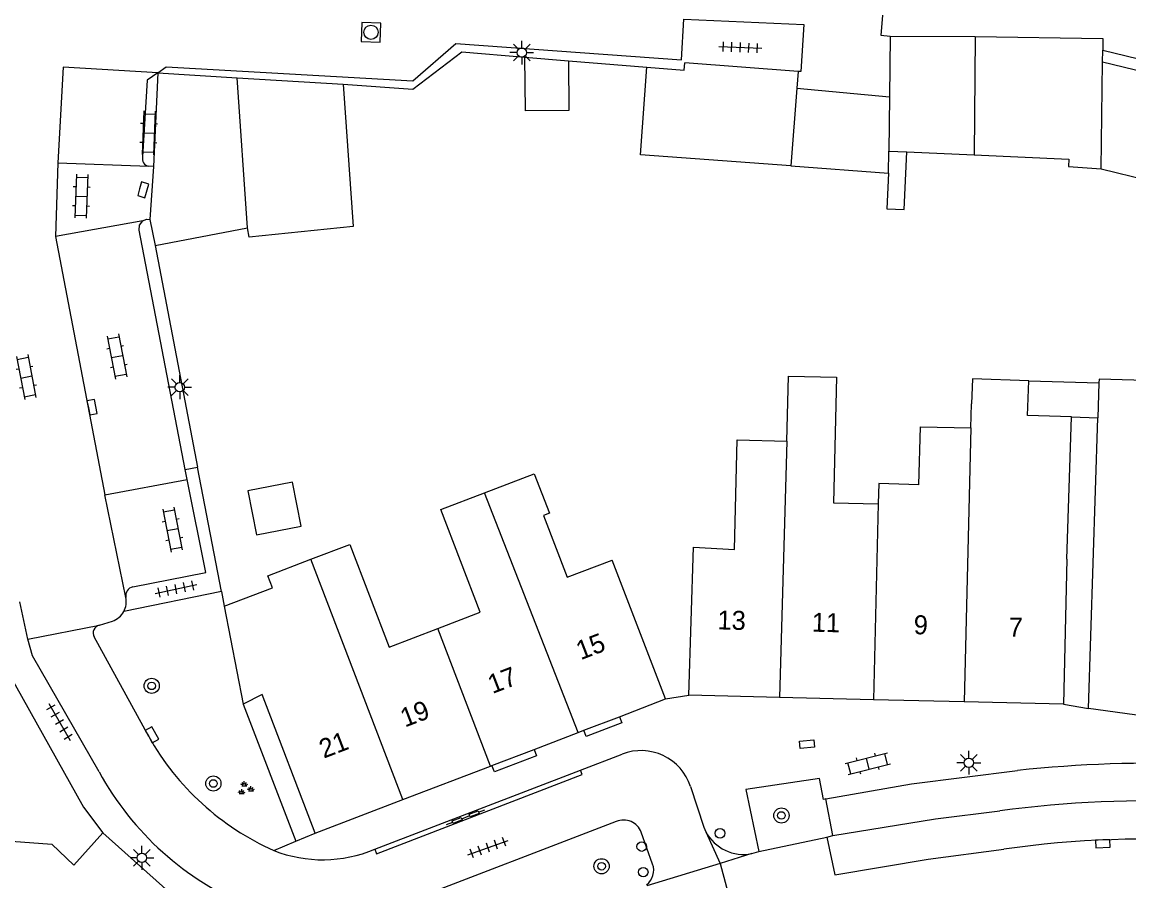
# Model space of a CAD drawing. Extents: x 132998 to 136004, y 396998 to 398512.
# Drawn here: x 133190.8 to 133249, y 397789.9 to 397835.1 of the extents above; entities that cross this region are included whole.
import ezdxf

# ---------------------------------------------------------------- set-up
doc = ezdxf.new("R2010")
doc.units = 0
for name, color, linetype in [('gg-afsc-erfafscheiding', 7, 'Continuous'), ('gg-afsc-muur', 7, 'Continuous'), ('gg-anno-huisnummerreeks BGT', 7, 'Continuous'), ('gg-bbg-bijgebouw', 7, 'Continuous'), ('gg-bbg-gedigitaliseerde bebouwing', 7, 'Continuous'), ('gg-bbg-gedigitaliseerde bijgebouw', 7, 'Continuous'), ('gg-bbg-hoofdgebouw', 7, 'Continuous'), ('gg-bbg-luifel en loopbrug', 7, 'Continuous'), ('gg-bbg-tussenscheiding', 7, 'Continuous'), ('gg-knt-verharding', 7, 'Continuous'), ('gg-knt-verharding nz', 7, 'Continuous'), ('gt-grn-afwateringsgoot', 7, 'Continuous'), ('gt-grn-weggrens', 7, 'Continuous'), ('gt-symb-afwateringsgoot', 7, 'Continuous'), ('gt-symb-boom', 7, 'Continuous'), ('gt-symb-drukknoppaal', 7, 'Continuous'), ('gt-symb-groenvak', 7, 'Continuous'), ('gt-symb-klinker verharding', 7, 'Continuous'), ('gt-symb-kolk', 7, 'Continuous'), ('gt-symb-kolk center center', 7, 'Continuous'), ('gt-symb-lichtmast', 7, 'Continuous'), ('gt-symb-rioolschacht', 7, 'Continuous'), ('gt-symb-tegel verharding', 7, 'Continuous'), ('gt-symb-verkeersregelinstallatiepaal', 7, 'Continuous')]:
    doc.layers.add(name, color=color, linetype=linetype)

# ---------------------------------------------------------------- blocks, each defined once
blk = doc.blocks.new('gt0-TEG1')
at = {"layer": 'gt-symb-tegel verharding'}
for p, q in [((-1.125, 0), (1.125, 0)), ((-0.9, -0.25), (-0.9, 0.25)), ((-0.45, -0.25), (-0.45, 0.25)), ((0, -0.25), (0, 0.25)), ((0.45, -0.25), (0.45, 0.25)), ((0.9, -0.25), (0.9, 0.25))]:
    blk.add_line(p, q, dxfattribs=at)
blk = doc.blocks.new('gt0-AFWGT_1')
at = {"layer": 'gt-symb-afwateringsgoot'}
for p, q in [((-1.076, 0), (-0.726, 0)), ((-0.225, 0), (0.225, 0)), ((0.725, 0), (1.075, 0))]:
    blk.add_line(p, q, dxfattribs=at)
for points in [[(-0.726, 0.075), (-0.225, 0.075), (-0.225, -0.075), (-0.726, -0.075)], [(0.225, 0.075), (0.725, 0.075), (0.725, -0.075), (0.225, -0.075)]]:
    blk.add_lwpolyline(points, close=True, dxfattribs=at)
blk = doc.blocks.new('gt0-LMAST')
at = {"layer": 'gt-symb-lichtmast'}
for p, q in [((-0.005, 0.246), (-0.005, 0.621)), ((-0.182, 0.173), (-0.447, 0.438)), ((0.172, 0.173), (0.437, 0.438)), ((-0.255, -0.004), (-0.63, -0.004)), ((-0.182, -0.181), (-0.447, -0.446)), ((-0.005, -0.254), (-0.005, -0.629)), ((0.437, -0.446), (0.172, -0.181)), ((0.245, -0.004), (0.62, -0.004))]:
    blk.add_line(p, q, dxfattribs=at)
blk.add_circle((-0.005, -0.004), 0.25, dxfattribs=at)
blk = doc.blocks.new('gt0-RS')
at = {"layer": 'gt-symb-rioolschacht'}
blk.add_lwpolyline([(-0.5, -0.5), (0.5, -0.5), (0.5, 0.5), (-0.5, 0.5)], close=True, dxfattribs=at)
blk.add_circle((0, 0), 0.375, dxfattribs=at)
blk = doc.blocks.new('gt0-KL1')
at = {"layer": 'gt-symb-klinker verharding'}
for p, q in [((-1.15, 0.3), (1.15, 0.3)), ((-1, -0.3), (-1, 0.3)), ((-0.5, 0.3), (-0.5, 0.45)), ((0, -0.3), (0, 0.3)), ((0.5, 0.3), (0.5, 0.45)), ((1, -0.3), (1, 0.3)), ((-1.15, -0.3), (1.15, -0.3)), ((-0.5, -0.45), (-0.5, -0.3)), ((0.5, -0.45), (0.5, -0.3))]:
    blk.add_line(p, q, dxfattribs=at)
blk = doc.blocks.new('gt0-KOLK')
at = {"layer": 'gt-symb-kolk'}
blk.add_lwpolyline([(0, 0), (0.375, 0), (0.375, 0.4), (-0.375, 0.4), (-0.375, 0), (0, 0)], dxfattribs=at)
blk = doc.blocks.new('gt0-BOOM')
at = {"layer": 'gt-symb-boom'}
for radius in [0.4, 0.2]:
    blk.add_circle((0, 0), radius, dxfattribs=at)
blk = doc.blocks.new('gt0-KOLKCC')
at = {"layer": 'gt-symb-kolk center center'}
blk.add_lwpolyline([(-0.375, 0.2), (0.375, 0.2), (0.375, -0.2), (-0.375, -0.2)], close=True, dxfattribs=at)
blk = doc.blocks.new('gt0-VIPAAL')
at = {"layer": 'gt-symb-verkeersregelinstallatiepaal'}
blk.add_circle((0, 0), 0.25, dxfattribs=at)
blk = doc.blocks.new('gt0-GRVAK')
at = {"layer": 'gt-symb-groenvak'}
for p, q in [((-0.11, 0.189), (-0.228, 0.24)), ((-0.182, 0.153), (0.088, 0.153)), ((-0.091, 0.211), (-0.156, 0.322)), ((-0.047, 0.214), (-0.047, 0.393)), ((-0.004, 0.211), (0.061, 0.322)), ((0.015, 0.189), (0.133, 0.24)), ((0.262, -0.052), (0.197, 0.059)), ((0.305, -0.049), (0.305, 0.13)), ((0.349, -0.052), (0.414, 0.059)), ((-0.245, -0.228), (-0.363, -0.177)), ((-0.318, -0.264), (-0.047, -0.264)), ((-0.226, -0.206), (-0.291, -0.095)), ((-0.183, -0.203), (-0.183, -0.024)), ((-0.139, -0.206), (-0.074, -0.095)), ((-0.12, -0.228), (-0.002, -0.177)), ((0.243, -0.074), (0.125, -0.023)), ((0.17, -0.11), (0.441, -0.11)), ((0.368, -0.074), (0.486, -0.023))]:
    blk.add_line(p, q, dxfattribs=at)
blk = doc.blocks.new('gt0-DPAAL')
at = {"layer": 'gt-symb-drukknoppaal'}
blk.add_circle((0, 0), 0.25, dxfattribs=at)

msp = doc.modelspace()

# ---------------------------------------------------------------- linework, layer by layer
at = {"layer": 'gg-afsc-erfafscheiding'}
for p, q in [((133219.534, 397833.102), (133223.664, 397832.759)), ((133197.777, 397823.375), (133200.006, 397811.718)), ((133201.273, 397805.159), (133200.006, 397811.718)), ((133201.273, 397805.159), (133201.422, 397804.389))]:
    msp.add_line(p, q, dxfattribs=at)
msp.add_lwpolyline([(133207.68, 397831.857), (133211.339, 397831.605), (133213.924, 397833.569), (133217.238, 397833.293)], dxfattribs=at)
at = {"layer": 'gg-afsc-muur'}
msp.add_lwpolyline([(133189.223, 397804.078), (133189.752, 397801.443), (133194.013, 397793.822), (133195.025, 397792.466)], dxfattribs=at)
at = {"layer": 'gg-bbg-bijgebouw'}
for p, q in [((133236.46, 397834.4), (133236.423, 397831.203)), ((133225.621, 397832.596), (133225.65, 397832.99)), ((133231.62, 397832.54), (133225.65, 397832.99)), ((133197.921, 397832.455), (133197.706, 397827.537)), ((133197.921, 397832.455), (133202.099, 397832.199)), ((133202.099, 397832.199), (133207.68, 397831.857)), ((133231.62, 397832.54), (133231.553, 397831.663)), ((133231.553, 397831.663), (133236.423, 397831.203)), ((133197.706, 397827.537), (133197.513, 397824.75)), ((133197.513, 397824.75), (133197.777, 397823.375))]:
    msp.add_line(p, q, dxfattribs=at)
msp.add_lwpolyline([(133236.28, 397838.22), (133235.97, 397834.45), (133236.46, 397834.4)], dxfattribs=at)
at = {"layer": 'gg-bbg-gedigitaliseerde bebouwing'}
for p, q in [((133247.449, 397816.142), (133247.39, 397814.304)), ((133240.715, 397813.775), (133240.746, 397815.037)), ((133245.763, 397806.866), (133246, 397814.365)), ((133246.9, 397799.01), (133247.39, 397814.304)), ((133215.111, 397810.358), (133217.735, 397811.363)), ((133245.763, 397806.866), (133245.58, 397799.23)), ((133201.422, 397804.389), (133202.422, 397799.232)), ((133203.422, 397799.747), (133202.422, 397799.232))]:
    msp.add_line(p, q, dxfattribs=at)
for points in [[(133231.019, 397813.081), (133231.108, 397816.501), (133233.638, 397816.439), (133233.472, 397809.84), (133235.829, 397809.783)], [(133243.754, 397816.259), (133240.788, 397816.353), (133240.746, 397815.037)], [(133246, 397814.365), (133243.696, 397814.437), (133243.754, 397816.259)], [(133250.496, 397816.253), (133247.456, 397816.349), (133247.449, 397816.142)], [(133237.977, 397810.783), (133238.051, 397813.84), (133240.715, 397813.775)], [(133226.108, 397807.493), (133228.277, 397807.369), (133228.418, 397813.144), (133231.019, 397813.081)], [(133217.735, 397811.363), (133218.532, 397809.283), (133218.226, 397809.166), (133219.468, 397805.916), (133221.838, 397806.821)], [(133237.977, 397810.783), (133235.863, 397810.85), (133235.829, 397809.783)], [(133212.658, 397803.219), (133214.886, 397804.072), (133212.816, 397809.479), (133215.111, 397810.358)], [(133205.98, 397806.862), (133208.025, 397807.645), (133210.095, 397802.238), (133212.658, 397803.219)], [(133201.422, 397804.389), (133203.964, 397805.362), (133203.721, 397805.997), (133205.98, 397806.862)]]:
    msp.add_lwpolyline(points, dxfattribs=at)
at = {"layer": 'gg-bbg-gedigitaliseerde bijgebouw'}
for p, q in [((133247.638, 397833.028), (133247.646, 397833.659)), ((133223.664, 397832.759), (133225.621, 397832.596)), ((133236.377, 397827.181), (133236.39, 397828.34)), ((133236.39, 397828.34), (133237.333, 397828.298)), ((133237.333, 397828.298), (133240.877, 397828.142)), ((133231.24, 397827.56), (133236.377, 397827.181)), ((133197.777, 397823.375), (133202.644, 397824.308))]:
    msp.add_line(p, q, dxfattribs=at)
for points in [[(133247.646, 397833.659), (133252.629, 397832.444), (133253.676, 397836.864), (133252.071, 397836.978)], [(133231.24, 397827.56), (133223.322, 397828.155), (133223.664, 397832.759)], [(133247.568, 397827.408), (133254.881, 397825.625), (133256.178, 397830.946), (133247.638, 397833.028)], [(133207.68, 397831.857), (133208.197, 397824.375), (133202.725, 397823.814), (133202.644, 397824.308)], [(133240.877, 397828.142), (133245.863, 397827.922), (133245.846, 397827.539), (133247.568, 397827.408)]]:
    msp.add_lwpolyline(points, dxfattribs=at)
at = {"layer": 'gg-bbg-hoofdgebouw'}
for p, q in [((133225.87, 397799.71), (133226.108, 397807.493)), ((133224.64, 397799.51), (133221.838, 397806.821)), ((133206.21, 397792.45), (133203.422, 397799.747)), ((133222.212, 397798.58), (133224.64, 397799.51)), ((133230.646, 397799.594), (133225.87, 397799.71)), ((133235.578, 397799.474), (133230.646, 397799.594)), ((133240.364, 397799.357), (133235.578, 397799.474)), ((133245.58, 397799.23), (133240.364, 397799.357)), ((133252.318, 397798.26), (133246.9, 397799.01)), ((133220.344, 397797.865), (133222.212, 397798.58)), ((133217.723, 397796.861), (133220.037, 397797.747)), ((133220.037, 397797.747), (133220.344, 397797.865)), ((133215.51, 397796.013), (133217.723, 397796.861)), ((133210.821, 397794.216), (133215.429, 397795.982)), ((133215.429, 397795.982), (133215.51, 397796.013)), ((133206.21, 397792.45), (133210.821, 397794.216)), ((133195.025, 397792.466), (133201.316, 397786.868))]:
    msp.add_line(p, q, dxfattribs=at)
msp.add_lwpolyline([(133182.882, 397792.565), (133192.357, 397791.868), (133193.511, 397790.761), (133195.025, 397792.466)], dxfattribs=at)
at = {"layer": 'gg-bbg-luifel en loopbrug'}
for p, q in [((133217.238, 397833.293), (133219.534, 397833.102)), ((133243.754, 397816.259), (133247.449, 397816.142)), ((133246, 397814.365), (133247.39, 397814.304))]:
    msp.add_line(p, q, dxfattribs=at)
for points in [[(133219.534, 397833.102), (133219.559, 397830.487), (133217.265, 397830.465), (133217.238, 397833.293)], [(133236.377, 397827.181), (133236.294, 397825.304), (133237.199, 397825.264), (133237.333, 397828.298)], [(133202.664, 397810.468), (133203.11, 397808.145), (133205.461, 397808.597), (133205.015, 397810.919), (133202.664, 397810.468)]]:
    msp.add_lwpolyline(points, dxfattribs=at)
at = {"layer": 'gg-bbg-tussenscheiding'}
for p, q in [((133236.46, 397834.4), (133240.939, 397834.372)), ((133240.939, 397834.372), (133240.877, 397828.142)), ((133247.568, 397827.408), (133247.638, 397833.028)), ((133202.644, 397824.308), (133202.099, 397832.199)), ((133231.553, 397831.663), (133231.24, 397827.56)), ((133236.423, 397831.203), (133236.39, 397828.34)), ((133240.715, 397813.775), (133240.364, 397799.357)), ((133231.019, 397813.081), (133230.646, 397799.594)), ((133220.037, 397797.747), (133215.111, 397810.358)), ((133235.829, 397809.783), (133235.578, 397799.474)), ((133210.821, 397794.216), (133205.98, 397806.862)), ((133215.429, 397795.982), (133212.658, 397803.219))]:
    msp.add_line(p, q, dxfattribs=at)
msp.add_lwpolyline([(133240.939, 397834.372), (133247.654, 397834.267), (133247.646, 397833.659)], dxfattribs=at)
at = {"layer": 'gg-knt-verharding'}
for p, q in [((133197.921, 397832.455), (133198.368, 397832.785)), ((133197.706, 397827.537), (133197.45, 397827.545)), ((133199.361, 397811.594), (133200.006, 397811.718)), ((133199.463, 397811.06), (133199.361, 397811.594)), ((133201.273, 397805.159), (133196.136, 397804.119)), ((133191.09, 397802.651), (133190.658, 397804.629)), ((133194.852, 397803.389), (133195.538, 397803.61)), ((133191.09, 397802.651), (133194.852, 397803.389)), ((133197.445, 397797.529), (133194.576, 397802.773)), ((133224.64, 397799.51), (133225.87, 397799.71)), ((133202.422, 397799.232), (133205.195, 397792.027)), ((133245.58, 397799.23), (133246.9, 397799.01)), ((133220.17, 397795.772), (133222.364, 397796.608)), ((133233.445, 397792.333), (133233.078, 397794.249)), ((133222.049, 397793.056), (133210.736, 397788.714)), ((133223.962, 397790.826), (133223.366, 397792.504)), ((133204.025, 397791.539), (133205.195, 397792.027)), ((133205.195, 397792.027), (133206.21, 397792.45)), ((133229.543, 397791.489), (133233.132, 397792.247)), ((133233.132, 397792.247), (133233.445, 397792.333)), ((133229.18, 397791.372), (133227.519, 397790.861)), ((133229.18, 397791.372), (133229.543, 397791.489)), ((133227.519, 397790.861), (133223.656, 397789.673))]:
    msp.add_line(p, q, dxfattribs=at)
for points in [[(133198.368, 397832.785), (133211.34, 397832.04), (133213.61, 397834), (133225.48, 397833.14), (133225.61, 397835.28), (133231.92, 397835.01), (133231.759, 397832.531), (133231.62, 397832.54)], [(133197.921, 397832.455), (133197.367, 397832.07), (133197.126, 397828.05)], [(133199.361, 397811.594), (133196.949, 397824.174), (133196.968, 397824.452), (133197.137, 397824.673)], [(133197.137, 397824.673), (133197.329, 397824.756), (133197.513, 397824.75)], [(133196.606, 397805.418), (133200.454, 397806.166), (133199.463, 397811.06)], [(133194.838, 397795.676), (133191.338, 397801.785), (133191.09, 397802.651)], [(133222.212, 397798.58), (133222.337, 397798.253), (133220.47, 397797.538), (133220.344, 397797.865)], [(133217.723, 397796.861), (133217.852, 397796.525), (133215.639, 397795.677), (133215.51, 397796.013)], [(133233.078, 397794.249), (133237.58, 397795.038), (133243.167, 397795.755)], [(133225.948, 397794.908), (133226.656, 397792.768), (133226.766, 397792.524)], [(133233.078, 397794.249), (133232.954, 397794.228), (133232.737, 397795.332), (133228.872, 397794.741), (133229.543, 397791.489)], [(133233.445, 397792.333), (133238.844, 397793.201), (133242.237, 397793.62)], [(133233.543, 397790.25), (133238.468, 397791.088), (133242.436, 397791.601)]]:
    msp.add_lwpolyline(points, dxfattribs=at)
for centre, radius, start, end in [((133197.51, 397827.94), 0.4, 164.02505, 261.34213), ((133196.729, 397804.943), 0.491, 104.4622, 190.62162), ((133195.173, 397804.638), 1.094, 331.65928, 11.27154), ((133195.174, 397804.644), 1.096, 289.41635, 331.39055), ((133194.941, 397802.979), 0.419, 102.24014, 209.49014), ((133209.821, 397804.515), 14.211, 209.4433, 245.93136), ((133223.357, 397794.073), 2.722, 17.86142, 111.38577), ((133250.365, 397726.886), 69.244, 87.8855, 95.96684), ((133208.806, 397803.301), 15.914, 208.63102, 247.59356), ((133250.106, 397735.644), 58.508, 87.26591, 97.72953), ((133222.446, 397792.155), 0.984, 20.75315, 113.76639), ((133228.746, 397793.569), 2.239, 207.81458, 281.16295), ((133249.875, 397740.234), 51.903, 85.64522, 98.24014), ((133206.602, 397798.061), 7.013, 248.44219, 293.00171), ((133223.049, 397790.499), 0.97, 307.55062, 19.70427)]:
    msp.add_arc(centre, radius, start, end, dxfattribs=at)
at = {"layer": 'gg-knt-verharding nz'}
for p, q in [((133192.671, 397827.722), (133197.45, 397827.545)), ((133197.137, 397824.673), (133192.543, 397823.846)), ((133192.543, 397823.846), (133195.139, 397810.259)), ((133195.139, 397810.259), (133199.463, 397811.06)), ((133196.246, 397804.852), (133195.139, 397810.259)), ((133226.766, 397792.524), (133227.519, 397790.861)), ((133233.132, 397792.247), (133233.543, 397790.25)), ((133227.519, 397790.861), (133228.843, 397785.832))]:
    msp.add_line(p, q, dxfattribs=at)
msp.add_lwpolyline([(133197.921, 397832.455), (133192.937, 397832.758), (133192.671, 397827.722)], dxfattribs=at)
at = {"layer": 'gt-grn-afwateringsgoot'}
msp.add_line((133209.342, 397791.606), (133220.17, 397795.772), dxfattribs=at)
msp.add_lwpolyline([(133209.342, 397791.606), (133209.44, 397791.368), (133220.261, 397795.528), (133220.17, 397795.772)], dxfattribs=at)
at = {"layer": 'gt-grn-weggrens'}
msp.add_line((133192.671, 397827.722), (133192.543, 397823.846), dxfattribs=at)

# ---------------------------------------------------------------- block references
at = {"layer": 'gt-symb-afwateringsgoot', "xscale": 0.9999900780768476, "yscale": 0.9999900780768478, "rotation": 21.031340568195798}
msp.add_blockref('gt0-AFWGT_1', (133214.125, 397793.293), dxfattribs=at)
at = {"layer": 'gt-symb-boom', "rotation": -79.34163849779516}
for p in [(133197.602, 397800.201), (133200.849, 397795.063)]:
    msp.add_blockref('gt0-BOOM', p, dxfattribs=at)
at = {"layer": 'gt-symb-boom'}
for p in [(133230.741, 397793.38), (133221.275, 397790.707)]:
    msp.add_blockref('gt0-BOOM', p, dxfattribs=at)
at = {"layer": 'gt-symb-drukknoppaal'}
msp.add_blockref('gt0-DPAAL', (133223.388, 397791.743), dxfattribs=at)
at = {"layer": 'gt-symb-groenvak'}
msp.add_blockref('gt0-GRVAK', (133202.523, 397794.792), dxfattribs=at)
at = {"layer": 'gt-symb-klinker verharding'}
for p, rotation in [((133197.444, 397829.3), -91.8919654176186), ((133193.9, 397825.968), -91.89196541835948), ((133195.777, 397817.535), -79.10581701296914), ((133191.003, 397816.453), -79.1620895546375), ((133198.698, 397808.426), -79.10581701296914), ((133235.286, 397796.107), 14.119602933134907)]:
    msp.add_blockref('gt0-KL1', p, dxfattribs=dict(at, rotation=rotation))
at = {"layer": 'gt-symb-kolk'}
for p, rotation in [((133196.97, 397826.362), -106.13420459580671), ((133194.269, 397814.827), -79.16208955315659), ((133197.445, 397797.529), -61.34123567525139), ((133247.648, 397792.09), -177.5377902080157)]:
    msp.add_blockref('gt0-KOLK', p, dxfattribs=dict(at, rotation=rotation))
at = {"layer": 'gt-symb-kolk center center', "rotation": -174.44758671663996}
msp.add_blockref('gt0-KOLKCC', (133232.088, 397797.133), dxfattribs=at)
at = {"layer": 'gt-symb-lichtmast'}
for p in [(133217.082, 397833.533), (133199.084, 397815.923), (133240.606, 397796.157), (133197.093, 397791.155)]:
    msp.add_blockref('gt0-LMAST', p, dxfattribs=at)
at = {"layer": 'gt-symb-rioolschacht', "rotation": 178.05074587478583}
msp.add_blockref('gt0-RS', (133209.141, 397834.597), dxfattribs=at)
at = {"layer": 'gt-symb-tegel verharding'}
for p, rotation in [((133228.577, 397833.801), -2.4646633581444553), ((133198.882, 397805.296), 11.950647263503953), ((133192.754, 397798.304), -59.92097413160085), ((133215.299, 397791.685), 19.93904791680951)]:
    msp.add_blockref('gt0-TEG1', p, dxfattribs=dict(at, rotation=rotation))
at = {"layer": 'gt-symb-verkeersregelinstallatiepaal'}
for p in [(133227.509, 397792.441), (133223.471, 397790.398)]:
    msp.add_blockref('gt0-VIPAAL', p, dxfattribs=at)

# ---------------------------------------------------------------- texts
at = {"layer": 'gg-anno-huisnummerreeks BGT'}
for s, rotation, p in [('13', 358.6, (133227.366, 397803.175)), ('11', 358.6, (133232.327, 397803.054)), ('9', 358.6, (133237.691, 397802.923)), ('7', 358.6, (133242.688, 397802.801)), ('15', 21, (133220.176, 397801.548)), ('17', 21, (133215.531, 397799.769)), ('19', 21, (133210.927, 397798.005)), ('21', 21, (133206.656, 397796.368))]:
    msp.add_text(s, height=1, rotation=rotation, dxfattribs=at).set_placement(p)

doc.saveas('drawing.dxf')
